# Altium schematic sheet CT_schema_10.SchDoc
size 287 x 160 mm
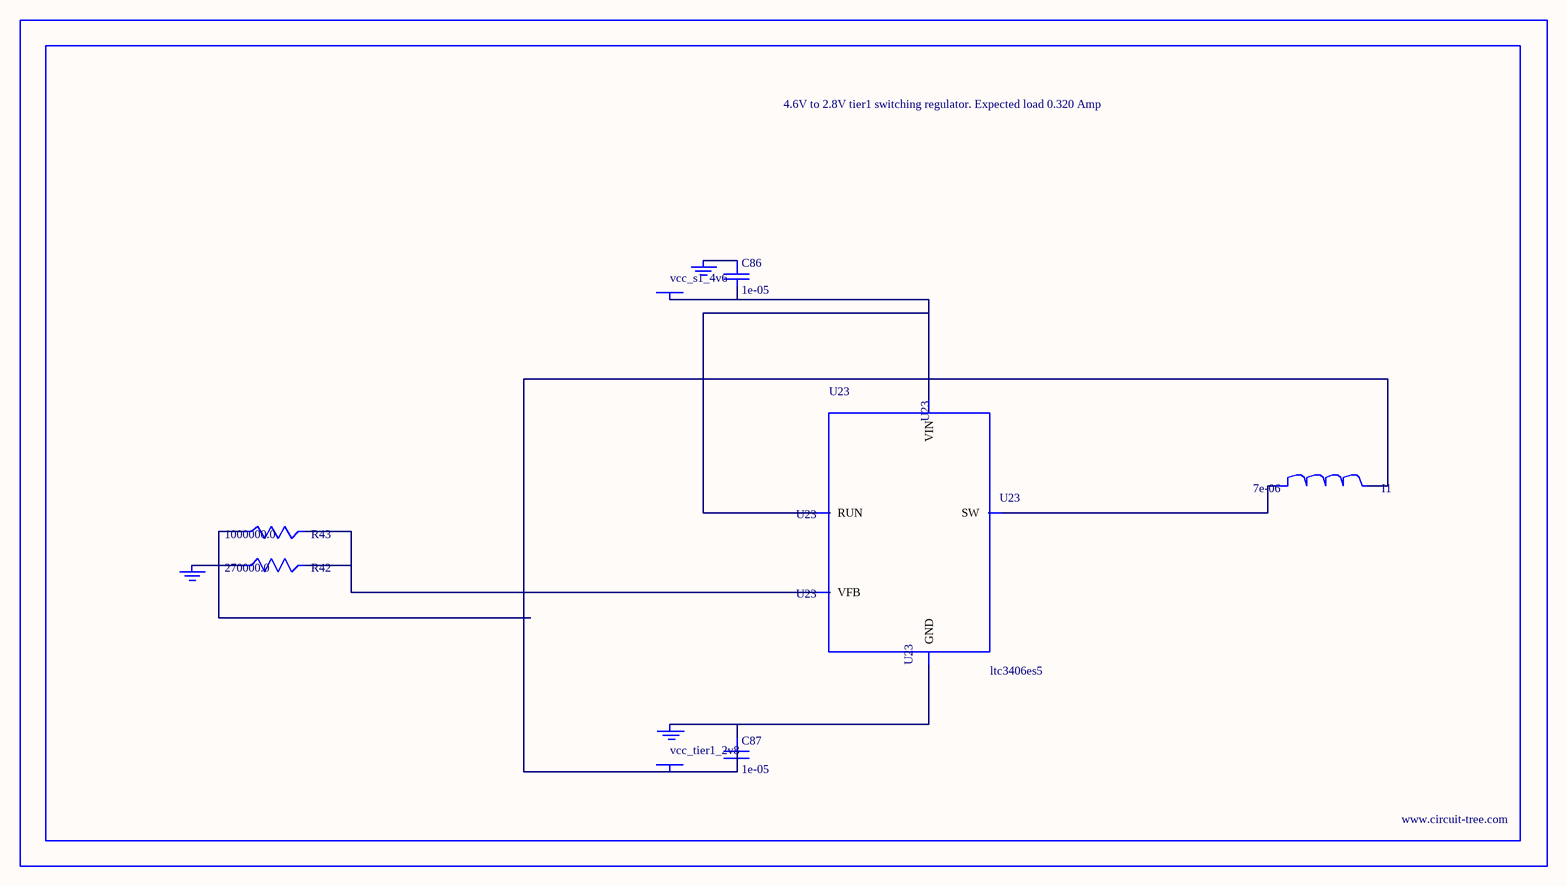
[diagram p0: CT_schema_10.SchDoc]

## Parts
BORDER9  (no value)
C86  1e-05  [C0805]
C87  1e-05  [C0805]
GND_INSTANCE_9_0  (no value)
GND_INSTANCE_9_1  (no value)
GND_INSTANCE_9_2  (no value)
I1  7e-06  [DR1040]
POWER_INSTANCE_9_0  vcc_tier1_2v8
POWER_INSTANCE_9_1  vcc_s1_4v6
R42  270000.0  [R0603]
R43  1000000.0  [R0603]
U23  ltc3406es5  [TSOT-23-5]

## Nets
NetC86_1: C86.1 GND_INSTANCE_9_1.0(GND)
NetC86_2: C86.2 POWER_INSTANCE_9_1.0(PWR) U23.1(RUN) U23.4(VIN)
NetC87_1: C87.1 GND_INSTANCE_9_0.0(GND) U23.2(GND)
NetC87_2: C87.2 I1.2 POWER_INSTANCE_9_0.0(PWR) R43.1
NetGND_INSTANCE_9_2_0: GND_INSTANCE_9_2.0(GND) R42.1
NetI1_1: I1.1 U23.3(SW)
NetR42_2: R42.2 R43.2 U23.5(VFB)

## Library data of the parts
BORDER9 = BORDER_PAGE9
C86 C87 = C0805C106K8RACTU
GND_INSTANCE_9_0-GND_INSTANCE_9_2 = GND
I1 = DR1040-7R0-R
POWER_INSTANCE_9_0 POWER_INSTANCE_9_1 = PWR
R42 = RC0603JR-07270KL
R43 = RC0603JR-071ML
